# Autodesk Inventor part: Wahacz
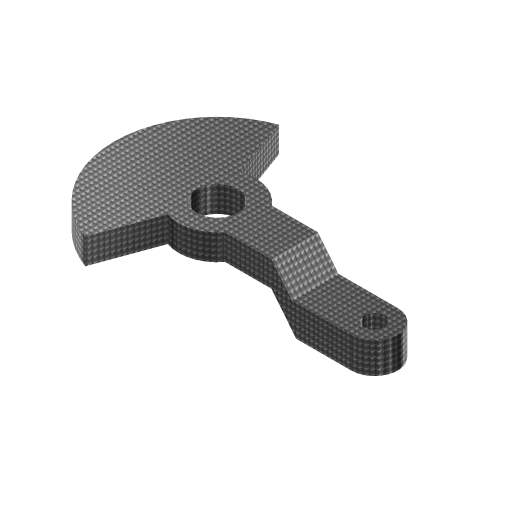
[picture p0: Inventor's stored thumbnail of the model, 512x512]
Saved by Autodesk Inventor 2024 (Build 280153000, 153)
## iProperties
Company: ATC
Shininess: 20.0
Angle Display Precision: 2
Document Length Units: 11269
Document Angle Units: 11279
Document Time Units: 11290
Document Mass Units: 11283
Document Length Units Precision: 3
Document Angle Units Precision: 2
Created: 2023-03
Part Number: Wahacz
Material: Stal węglowa
Document SubType Name: Modelowanie
Designer: Andrzej Jaskulski
Density: 7.87 g/cm^3
Stock Number: Wahacz
Mass: 326.35 g
Surface Area: 107.803 cm^2
Volume: 32.635 cm^3
Appearance: Pokryte liniami
Checked By: A.J.
Engr Approved By: Andrzej Jaskulski
Mfg Approved By: Andrzej Jaskulski
Authority: A.J.
Density: 0.0
Volumn: 0.0
Area: 0.0
PropertySet Name: Model Information
Control State: 0
Master: False
Checked Out: False
Title: A.J.: Kurs R2024-MEP
Author: Andrzej Jaskulski
Revision Number: 1/24
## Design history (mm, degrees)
sketch "Szkic1"
  geometry: L1 (36.371, 18.985)-(54.371, 18.985); L2 (36.371, 0.985)-(54.371, 0.985); L3 (19.241, -4.11)-(10.691, -27.603); L4 (19.241, 24.081)-(10.691, 47.573); L5 (-41.915, 9.985)-(91.63, 9.985); L6 (54.371, 0.985)-(54.371, 18.985); L7 (19.241, -4.11)-(24.371, 9.985); L8 (19.241, 24.081)-(24.371, 9.985); C1 r 8 at (24.371, 9.985); C2 r 4 at (-11.629, 9.985); A1 r 15 centre (24.371, 9.985) between (19.241, 24.081) and (19.241, -4.11); A2 r 40 centre (24.371, 9.985) between (10.691, 47.573) and (10.691, -27.603)
  constraints: 16 end point, 6 point on circle, 4 centre point, 2 collinear, 2 point on line, 1 coincident, 1 concentric, 1 horizontal, 1 parallel, 1 perpendicular, 1 tangent, 3 other
  dimensions: "d4" = 40 radius of A2; "d5" = 30 diameter of A1; "d6" = 16 diameter of C1; "d7" = 8 diameter of C2; "d22" = 140 deg angle of L3 L4; "d23" = 30 distance from line of L6 C1.centre; "d24" = 18 distance of L2.end L1.end
extrude "Wyciągnięcie proste1" new body sketch "Szkic1" distance "d2" = 10; taper "d3" = 0 deg
extrude "Wyciągnięcie proste2" join sketch "Szkic1" distance "d8" = 12; taper "d9" = 0 deg
extrude "Wyciągnięcie proste3" cut sketch "Szkic1" extent not by distance; stored distance "d12" = 12; taper "d13" = 0 deg
sketch "Szkic5"
  geometry: L1 (30, 0)-(30, 10) reference; L2 (30, 10)-(38, 0); L3 (38, 0)-(70, 0); L4 (70, 0)-(70, -12); L5 (70, -12)-(39.6, -12); L6 (39.6, -12)-(30, 0); L7 (0, -16.4)-(0, 14.4) reference
  constraints: 10 end point, 3 perpendicular, 1 parallel, 1 point on line
  dimensions: "d19" = 12 distance between parallel lines of L3 L5; "d20" = 38 distance from line of L2.end L7; "d28" = 70 distance between parallel lines of L4 L7
extrude "Wyciągnięcie proste5" join sketch "Szkic5" stored distance "d25" = 17.57962; taper "d26" = 0 deg
fillet "Zaokrąglenie1" dims "d27" = 9
sketch "Szkic6"
  geometry: A1 r 9 centre (23, 9) between (23, 0) and (23, 18) reference; 1 further point
hole "Otwór1" sketch "Szkic6" diameter "d30" = 8; stored, may be unused: countersink angle "d34" = 82 deg, drill point angle "d36" = 118 deg; dims "d31" = 6, "d32" = 4, "d33" = 2, "d35" = 8
node "Bryła1"
node "Korpusy bryłowe"
node "Korpusy powierzchniowe"
node "Początek"
node "Oś konstrukcyjna1"
node "Płaszczyzna konstrukcyjna2"
node "Płaszczyzna YZ"
node "Płaszczyzna XZ"
node "Płaszczyzna XY"
node "Oś X"
node "Oś Y"
node "Oś Z"
node "Punkt środkowy"
other parameters: "d0" = 110 deg, "d18" = 0
